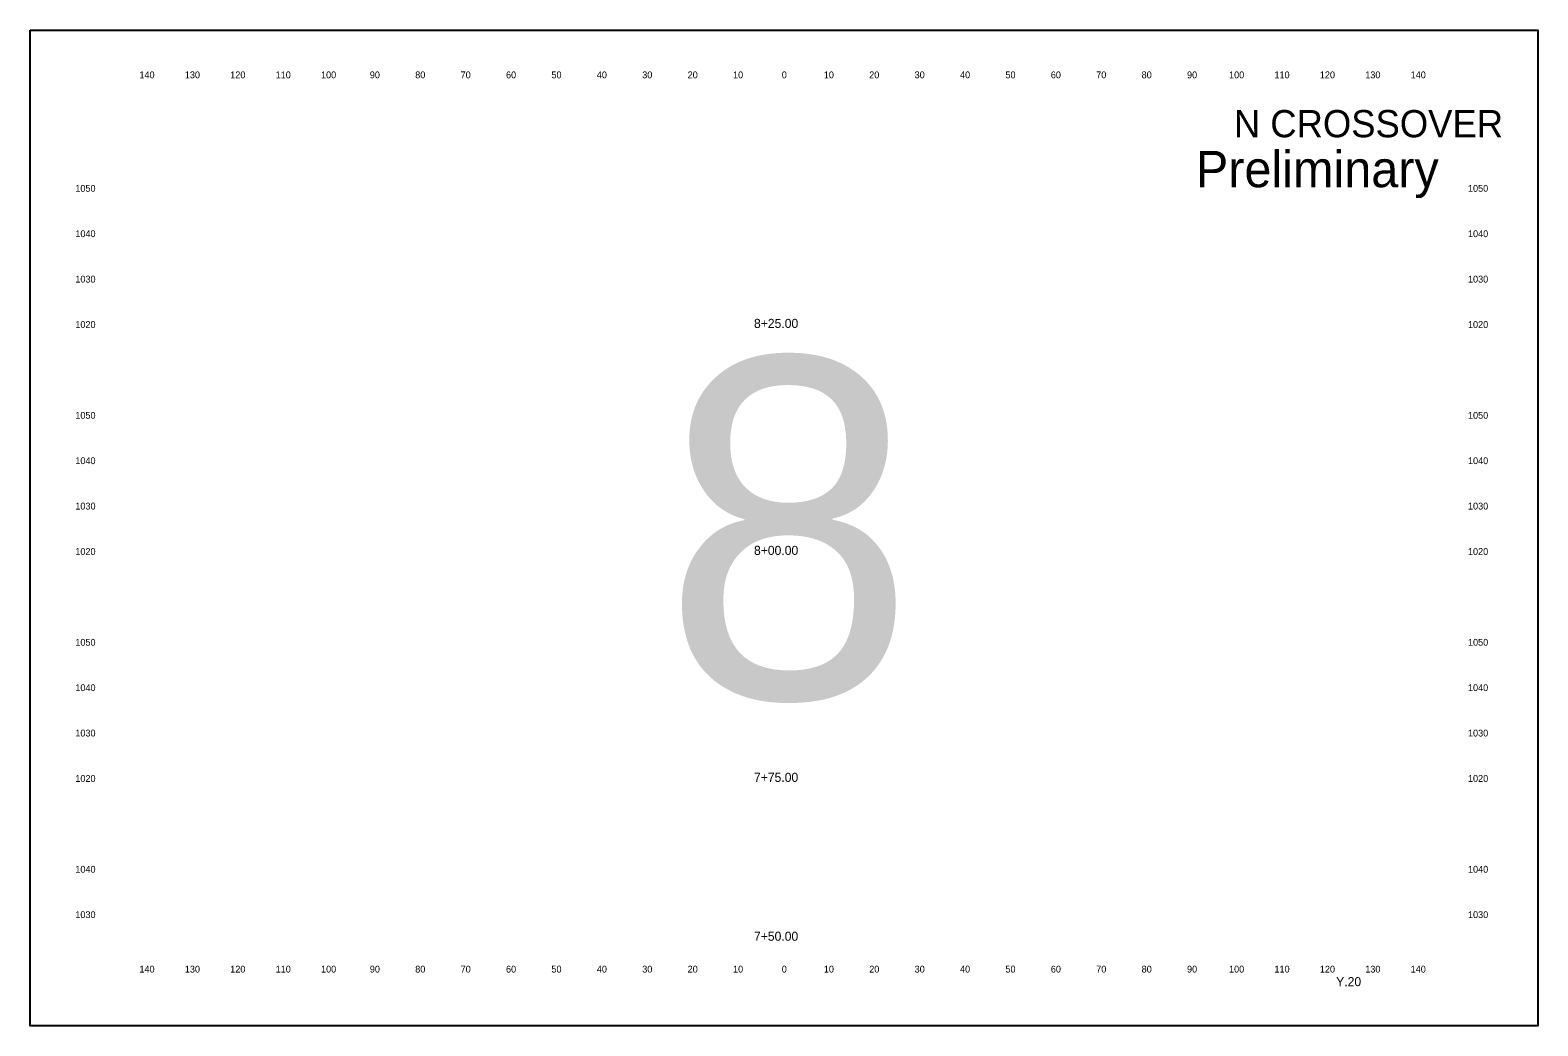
# Model space of a CAD drawing. Extents: x 10123 to 14767, y 9730 to 9950.
# Drawn here: x 12643.2 to 12975.3, y 9730.3 to 9949.6 of the extents above; entities that cross this region are included whole.
import ezdxf

# ---------------------------------------------------------------- set-up
doc = ezdxf.new("R2010")
doc.units = 0
for name, color, linetype in [('dsnTextCpn', 7, 'Continuous'), ('dsnTextCpnTitleSheetLocDesc', 7, 'Continuous'), ('dsnTextCpnTitleSheetPIN', 7, 'Continuous'), ('dsnTextCpnTitleSheetWorkType', 7, 'Continuous')]:
    doc.layers.add(name, color=color, linetype=linetype)

msp = doc.modelspace()

# ---------------------------------------------------------------- linework, layer by layer
at = {"layer": 'dsnTextCpnTitleSheetWorkType'}
msp.add_lwpolyline([(12643.21, 9949.6), (12975.29, 9949.6), (12975.29, 9730.26), (12643.21, 9730.26)], close=True, dxfattribs=at)

# ---------------------------------------------------------------- texts
at = {"layer": 'dsnTextCpn'}
for s, height, p in [('140', 1.5, (12667.27, 9939)), ('130', 1.5, (12677.27, 9939)), ('120', 1.5, (12687.27, 9939)), ('110', 1.5, (12697.27, 9939)), ('100', 1.5, (12707.27, 9939)), ('90', 1.5, (12718.02, 9939)), ('80', 1.5, (12728.02, 9939)), ('70', 1.5, (12738.02, 9939)), ('60', 1.5, (12748.02, 9939)), ('50', 1.5, (12758.02, 9939)), ('40', 1.5, (12768.02, 9939)), ('30', 1.5, (12778.02, 9939)), ('20', 1.5, (12788.02, 9939)), ('10', 1.5, (12798.02, 9939)), ('0', 1.5, (12808.76, 9939)), ('0', 1.5, (12808.76, 9939)), ('10', 1.5, (12818.02, 9939)), ('20', 1.5, (12828.02, 9939)), ('30', 1.5, (12838.02, 9939)), ('40', 1.5, (12848.02, 9939)), ('50', 1.5, (12858.02, 9939)), ('60', 1.5, (12868.02, 9939)), ('70', 1.5, (12878.02, 9939)), ('80', 1.5, (12888.02, 9939)), ('90', 1.5, (12898.02, 9939)), ('100', 1.5, (12907.27, 9939)), ('110', 1.5, (12917.27, 9939)), ('120', 1.5, (12927.27, 9939)), ('130', 1.5, (12937.27, 9939)), ('140', 1.5, (12947.27, 9939)), ('N CROSSOVER', 6, (12908.34, 9926)), ('1050', 1.5, (12653.15, 9914)), ('1050', 1.5, (12959.9, 9914)), ('1040', 1.5, (12653.15, 9904)), ('1040', 1.5, (12959.9, 9904)), ('1030', 1.5, (12653.15, 9894)), ('1030', 1.5, (12959.9, 9894)), ('1020', 1.5, (12653.15, 9884)), ('8+25.00', 2, (12802.64, 9884)), ('1020', 1.5, (12959.9, 9884)), ('1050', 1.5, (12653.15, 9864)), ('1050', 1.5, (12959.9, 9864)), ('1040', 1.5, (12653.15, 9854)), ('1040', 1.5, (12959.9, 9854)), ('1030', 1.5, (12653.15, 9844)), ('1030', 1.5, (12959.9, 9844)), ('1020', 1.5, (12653.15, 9834)), ('8+00.00', 2, (12802.64, 9834)), ('1020', 1.5, (12959.9, 9834)), ('1050', 1.5, (12653.15, 9814)), ('1050', 1.5, (12959.9, 9814)), ('1040', 1.5, (12653.15, 9804)), ('1040', 1.5, (12959.9, 9804)), ('1030', 1.5, (12653.15, 9794)), ('1030', 1.5, (12959.9, 9794)), ('1020', 1.5, (12653.15, 9784)), ('7+75.00', 2, (12802.64, 9784)), ('1020', 1.5, (12959.9, 9784)), ('1040', 1.5, (12653.15, 9764)), ('1040', 1.5, (12959.9, 9764)), ('1030', 1.5, (12653.15, 9754)), ('1030', 1.5, (12959.9, 9754)), ('7+50.00', 2, (12802.64, 9749)), ('140', 1.5, (12667.27, 9742)), ('130', 1.5, (12677.27, 9742)), ('120', 1.5, (12687.27, 9742)), ('110', 1.5, (12697.27, 9742)), ('100', 1.5, (12707.27, 9742)), ('90', 1.5, (12718.02, 9742)), ('80', 1.5, (12728.02, 9742)), ('70', 1.5, (12738.02, 9742)), ('60', 1.5, (12748.02, 9742)), ('50', 1.5, (12758.02, 9742)), ('40', 1.5, (12768.02, 9742)), ('30', 1.5, (12778.02, 9742)), ('20', 1.5, (12788.02, 9742)), ('10', 1.5, (12798.02, 9742)), ('0', 1.5, (12808.76, 9742)), ('0', 1.5, (12808.76, 9742)), ('10', 1.5, (12818.02, 9742)), ('20', 1.5, (12828.02, 9742)), ('30', 1.5, (12838.02, 9742)), ('40', 1.5, (12848.02, 9742)), ('50', 1.5, (12858.02, 9742)), ('60', 1.5, (12868.02, 9742)), ('70', 1.5, (12878.02, 9742)), ('80', 1.5, (12888.02, 9742)), ('90', 1.5, (12898.02, 9742)), ('100', 1.5, (12907.27, 9742)), ('110', 1.5, (12917.27, 9742)), ('120', 1.5, (12927.27, 9742)), ('130', 1.5, (12937.27, 9742)), ('140', 1.5, (12947.27, 9742))]:
    msp.add_text(s, height=height, dxfattribs=at).set_placement(p)
at = {"layer": 'dsnTextCpnTitleSheetLocDesc'}
msp.add_text('Preliminary', height=8, dxfattribs=at).set_placement((12899.97, 9915))
at = {"layer": 'dsnTextCpnTitleSheetPIN'}
msp.add_text('Y.20', height=2, dxfattribs=at).set_placement((12930.87, 9739))
at = {"layer": 'dsnTextCpnTitleSheetWorkType'}
msp.add_text('8', height=75, dxfattribs=at).set_placement((12782.42, 9802.43))

doc.saveas('drawing.dxf')
